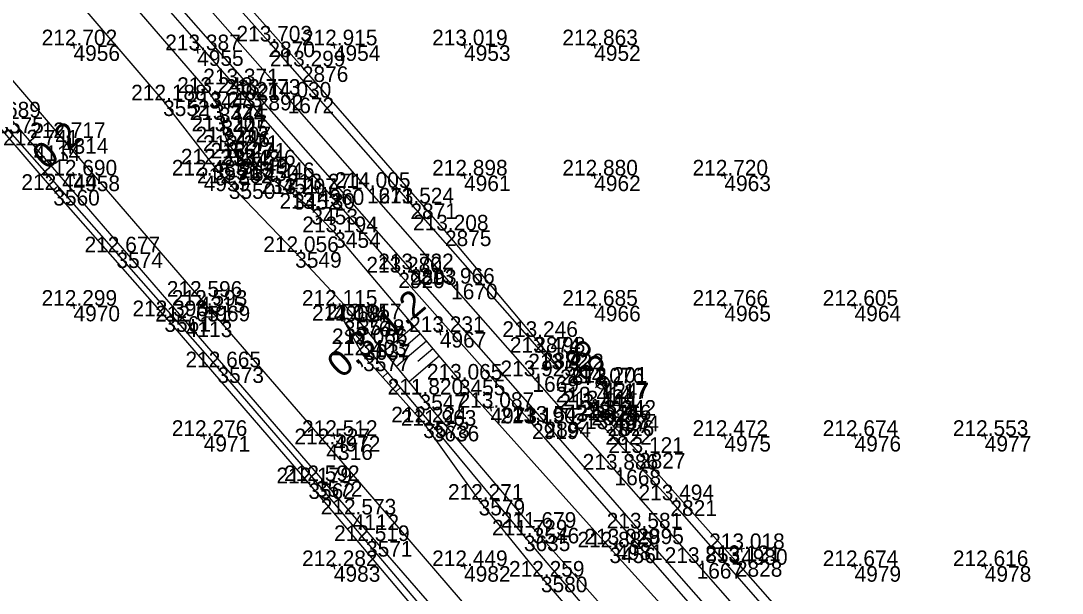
# Model space of a CAD drawing. Extents: x -556590 to -554855, y -1137918 to -1135717.
# Drawn here: x -555704 to -555624.1, y -1136452.1 to -1136408.1 of the extents above; entities that cross this region are included whole.
import ezdxf

# ---------------------------------------------------------------- set-up
doc = ezdxf.new("R2010")
doc.units = 0
for name, color, linetype in [('Vrstva 1', 7, 'Continuous'), ('Vrstva 11', 7, 'Continuous'), ('Vrstva 4', 7, 'Continuous'), ('Vrstva 48', 7, 'Continuous'), ('Vrstva 49', 7, 'Continuous'), ('Vrstva 51', 7, 'Continuous'), ('Vrstva 60', 7, 'Continuous'), ('Vrstva 61', 7, 'Continuous'), ('Vrstva 7', 7, 'Continuous')]:
    doc.layers.add(name, color=color, linetype=linetype)

msp = doc.modelspace()

# ---------------------------------------------------------------- linework, layer by layer
at = {"layer": 'Vrstva 1'}
msp.add_lwpolyline([(-555617.047, -1136489.655), (-555624.151, -1136481.584), (-555631.492, -1136473.245), (-555638.201, -1136465.612), (-555645.14, -1136457.724), (-555652.139, -1136449.756), (-555658.441, -1136442.59), (-555664.747, -1136435.415), (-555670.993, -1136428.307), (-555677.463, -1136420.947), (-555683.552, -1136414.017), (-555690.44, -1136406.179)], dxfattribs=at)
at = {"layer": 'Vrstva 11'}
for p, q in [((-555659.695, -1136435.535), (-555659.031, -1136436.291)), ((-555658.947, -1136435.632), (-555659.65, -1136435.587)), ((-555658.873, -1136436.013), (-555659.3, -1136435.985))]:
    msp.add_line(p, q, dxfattribs=at)
msp.add_circle((-555659.363, -1136435.913), 0.503, dxfattribs=at)
msp.add_arc((-555659.363, -1136435.913), 0.503, 311.31175, 131.31175, dxfattribs=at)
at = {"layer": 'Vrstva 4'}
for points in [[(-555622.431, -1136487.275), (-555632.955, -1136475.376), (-555645.659, -1136460.876), (-555652.243, -1136453.349), (-555664.779, -1136439.038), (-555675.055, -1136427.452), (-555687.678, -1136412.993), (-555700.952, -1136397.803)], [(-555696.06, -1136397.354), (-555685.031, -1136409.707), (-555674.12, -1136422.141), (-555664.029, -1136433.605), (-555662.623, -1136434.886), (-555664.606, -1136432.398), (-555671.469, -1136424.221), (-555682.46, -1136411.616), (-555693.764, -1136398.888)], [(-555697.757, -1136400.334), (-555685.919, -1136413.799), (-555674.147, -1136427.201), (-555663.818, -1136438.907), (-555656.688, -1136447.108), (-555646.98, -1136458.141), (-555633.977, -1136472.931), (-555622.465, -1136485.967)], [(-555620.12, -1136483.808), (-555629.064, -1136473.626), (-555637.092, -1136464.514), (-555645.582, -1136454.683), (-555654.149, -1136444.941), (-555659.148, -1136439.478), (-555660.228, -1136437.983), (-555660.506, -1136437.427), (-555660.012, -1136437.729), (-555658.962, -1136438.799), (-555656.562, -1136441.303), (-555649.119, -1136449.615), (-555638.104, -1136462.15), (-555629.912, -1136471.616), (-555620.889, -1136481.776)]]:
    msp.add_lwpolyline(points, dxfattribs=at)
at = {"layer": 'Vrstva 48'}
for p, q in [((-555702.177, -1136419.705), (-555702.509, -1136419.998)), ((-555701.68, -1136420.267), (-555701.85, -1136420.417)), ((-555701.184, -1136420.829), (-555701.529, -1136421.134)), ((-555700.687, -1136421.391), (-555700.86, -1136421.544)), ((-555700.19, -1136421.953), (-555700.538, -1136422.26)), ((-555673.855, -1136431.59), (-555676.13, -1136433.514)), ((-555673.371, -1136432.163), (-555674.512, -1136433.128)), ((-555672.886, -1136432.735), (-555675.179, -1136434.674)), ((-555677.25, -1136434.383), (-555676.816, -1136433.995)), ((-555671.918, -1136433.881), (-555674.228, -1136435.835)), ((-555672.402, -1136433.308), (-555673.553, -1136434.281)), ((-555676.749, -1136434.942), (-555676.541, -1136434.755)), ((-555676.248, -1136435.5), (-555675.848, -1136435.141)), ((-555675.747, -1136436.059), (-555675.556, -1136435.887)), ((-555675.247, -1136436.617), (-555674.88, -1136436.288))]:
    msp.add_line(p, q, dxfattribs=at)
at = {"layer": 'Vrstva 49'}
for p, q in [((-555699.754, -1136409.953), (-555700.246, -1136410.047)), ((-555700.047, -1136409.754), (-555699.953, -1136410.246)), ((-555679.754, -1136409.953), (-555680.246, -1136410.047)), ((-555680.047, -1136409.754), (-555679.953, -1136410.246)), ((-555669.754, -1136409.953), (-555670.246, -1136410.047)), ((-555670.047, -1136409.754), (-555669.953, -1136410.246)), ((-555659.754, -1136409.953), (-555660.246, -1136410.047)), ((-555660.047, -1136409.754), (-555659.953, -1136410.246)), ((-555690.257, -1136410.331), (-555690.749, -1136410.425)), ((-555690.55, -1136410.132), (-555690.456, -1136410.624)), ((-555699.754, -1136419.953), (-555700.246, -1136420.047)), ((-555700.047, -1136419.754), (-555699.953, -1136420.246)), ((-555689.754, -1136419.953), (-555690.246, -1136420.047)), ((-555690.047, -1136419.754), (-555689.953, -1136420.246)), ((-555669.754, -1136419.953), (-555670.246, -1136420.047)), ((-555670.047, -1136419.754), (-555669.953, -1136420.246)), ((-555659.754, -1136419.953), (-555660.246, -1136420.047)), ((-555660.047, -1136419.754), (-555659.953, -1136420.246)), ((-555649.754, -1136419.953), (-555650.246, -1136420.047)), ((-555650.047, -1136419.754), (-555649.953, -1136420.246)), ((-555680.987, -1136421.014), (-555681.479, -1136421.108)), ((-555681.28, -1136420.815), (-555681.186, -1136421.307)), ((-555699.754, -1136429.953), (-555700.246, -1136430.047)), ((-555700.047, -1136429.754), (-555699.953, -1136430.246)), ((-555689.754, -1136429.953), (-555690.246, -1136430.047)), ((-555690.047, -1136429.754), (-555689.953, -1136430.246)), ((-555679.754, -1136429.953), (-555680.246, -1136430.047)), ((-555680.047, -1136429.754), (-555679.953, -1136430.246)), ((-555659.754, -1136429.953), (-555660.246, -1136430.047)), ((-555660.047, -1136429.754), (-555659.953, -1136430.246)), ((-555649.754, -1136429.953), (-555650.246, -1136430.047)), ((-555650.047, -1136429.754), (-555649.953, -1136430.246)), ((-555639.754, -1136429.953), (-555640.246, -1136430.047)), ((-555640.047, -1136429.754), (-555639.953, -1136430.246)), ((-555671.615, -1136431.97), (-555672.107, -1136432.064)), ((-555671.908, -1136431.771), (-555671.814, -1136432.263)), ((-555667.722, -1136437.796), (-555668.214, -1136437.89)), ((-555668.015, -1136437.597), (-555667.921, -1136438.089)), ((-555658.356, -1136438.4), (-555658.848, -1136438.494)), ((-555658.649, -1136438.201), (-555658.555, -1136438.693)), ((-555689.754, -1136439.953), (-555690.246, -1136440.047)), ((-555690.047, -1136439.754), (-555689.953, -1136440.246)), ((-555679.754, -1136439.953), (-555680.246, -1136440.047)), ((-555680.047, -1136439.754), (-555679.953, -1136440.246)), ((-555649.754, -1136439.953), (-555650.246, -1136440.047)), ((-555650.047, -1136439.754), (-555649.953, -1136440.246)), ((-555639.754, -1136439.953), (-555640.246, -1136440.047)), ((-555640.047, -1136439.754), (-555639.953, -1136440.246)), ((-555629.754, -1136439.953), (-555630.246, -1136440.047)), ((-555630.047, -1136439.754), (-555629.953, -1136440.246)), ((-555658.059, -1136448.282), (-555658.551, -1136448.376)), ((-555658.352, -1136448.083), (-555658.258, -1136448.575)), ((-555648.47, -1136448.645), (-555648.962, -1136448.739)), ((-555648.763, -1136448.446), (-555648.669, -1136448.938)), ((-555679.754, -1136449.953), (-555680.246, -1136450.047)), ((-555680.047, -1136449.754), (-555679.953, -1136450.246)), ((-555669.754, -1136449.953), (-555670.246, -1136450.047)), ((-555670.047, -1136449.754), (-555669.953, -1136450.246)), ((-555639.754, -1136449.953), (-555640.246, -1136450.047)), ((-555640.047, -1136449.754), (-555639.953, -1136450.246)), ((-555629.754, -1136449.953), (-555630.246, -1136450.047)), ((-555630.047, -1136449.754), (-555629.953, -1136450.246))]:
    msp.add_line(p, q, dxfattribs=at)
for points in [[(-555615.08, -1136504.35), (-555624.636, -1136493.356), (-555633.501, -1136483.078), (-555640.265, -1136476.113), (-555648.785, -1136465.606), (-555653.585, -1136459.624), (-555664.726, -1136447.055), (-555673.42, -1136436.82), (-555678.151, -1136431.048), (-555682.973, -1136425.879), (-555688.067, -1136420.591), (-555689.304, -1136419.148), (-555693.118, -1136414.231), (-555703.25, -1136402.376)], [(-555698.73, -1136403.047), (-555689.586, -1136413.659), (-555688.83, -1136414.76), (-555688.628, -1136415.732), (-555688.486, -1136416.605), (-555688.179, -1136417.451), (-555687.7, -1136418.11), (-555687.113, -1136418.693), (-555686.288, -1136419.221), (-555684.835, -1136420.199), (-555683.123, -1136421.418), (-555681.726, -1136422.558), (-555679.975, -1136424.355), (-555670.399, -1136435.676), (-555658.834, -1136448.566), (-555650.327, -1136457.954)], [(-555643.618, -1136487.596), (-555644.451, -1136486.193), (-555652.029, -1136477.665), (-555657.009, -1136471.916), (-555667.622, -1136459.78), (-555677.531, -1136448.072), (-555681.376, -1136443.471), (-555688.944, -1136434.731), (-555696.701, -1136425.902), (-555705.857, -1136415.541), (-555707.805, -1136413.856)], [(-555707.805, -1136413.856), (-555701.555, -1136421.104), (-555693.021, -1136430.806), (-555681.957, -1136443.636), (-555672.551, -1136454.774), (-555659.833, -1136469.457), (-555649.952, -1136480.634), (-555643.618, -1136487.596)], [(-555679.234, -1136431.158), (-555677.752, -1136433.823), (-555673.144, -1136438.962), (-555668.881, -1136444.904), (-555664.096, -1136450.807), (-555655.601, -1136460.682), (-555649.17, -1136468.098), (-555646.587, -1136471.361), (-555645.564, -1136473.014), (-555644.747, -1136474.497), (-555643.95, -1136475.423), (-555642.94, -1136476.222), (-555641.262, -1136477.392), (-555640.019, -1136478.677), (-555635.816, -1136483.63), (-555627.575, -1136492.996), (-555620.189, -1136501.785)], [(-555619.626, -1136500.541), (-555625.788, -1136493.44), (-555635.233, -1136482.747), (-555640.706, -1136476.683), (-555642.014, -1136475.54), (-555642.886, -1136474.933), (-555643.62, -1136474.334), (-555644.179, -1136473.51), (-555644.832, -1136472.269), (-555645.899, -1136470.755), (-555648.036, -1136467.768), (-555654.446, -1136460.474), (-555665.404, -1136447.647), (-555672.407, -1136439.217), (-555677.696, -1136432.953), (-555679.234, -1136431.158)]]:
    msp.add_lwpolyline(points, dxfattribs=at)
at = {"layer": 'Vrstva 51'}
for points in [[(-555743.133, -1136368.314), (-555733.406, -1136379.475), (-555727.162, -1136386.762), (-555718.214, -1136397.183), (-555709.998, -1136406.534), (-555700.89, -1136417.124), (-555690.385, -1136429.309), (-555680.58, -1136440.643), (-555668.402, -1136454.771), (-555656.288, -1136468.58), (-555643.895, -1136482.917), (-555632.798, -1136495.751), (-555617.483, -1136513.593), (-555605.979, -1136526.789), (-555593.57, -1136541.12), (-555579.464, -1136557.45), (-555567.58, -1136571.183), (-555555.68, -1136584.796), (-555545.666, -1136596.303), (-555537.365, -1136605.817), (-555530.457, -1136613.715), (-555520.191, -1136625.354), (-555507.504, -1136639.736)], [(-555505.522, -1136644.883), (-555519.562, -1136629.073), (-555531.744, -1136615.155), (-555540.175, -1136605.5), (-555547.673, -1136596.899), (-555556.471, -1136586.787), (-555567.721, -1136573.974), (-555575.942, -1136564.513), (-555582.917, -1136556.401), (-555594.357, -1136543.153), (-555603.925, -1136532.234), (-555617.682, -1136516.291), (-555630.463, -1136501.491), (-555643.583, -1136486.305), (-555657.513, -1136470.232), (-555666.727, -1136459.683), (-555678.561, -1136446.033), (-555691.372, -1136431.214), (-555703.054, -1136417.695), (-555713.773, -1136405.268), (-555725.819, -1136391.439), (-555738.306, -1136376.946), (-555744.231, -1136369.998)]]:
    msp.add_lwpolyline(points, dxfattribs=at)
at = {"layer": 'Vrstva 60'}
for p, q in [((-555700, -1136410), (-555700, -1136410)), ((-555685.031, -1136409.707), (-555685.031, -1136409.707)), ((-555680, -1136410), (-555680, -1136410)), ((-555670, -1136410), (-555670, -1136410)), ((-555660, -1136410), (-555660, -1136410)), ((-555690.503, -1136410.378), (-555690.503, -1136410.378)), ((-555682.46, -1136411.616), (-555682.46, -1136411.616)), ((-555687.678, -1136412.993), (-555687.678, -1136412.993)), ((-555689.586, -1136413.659), (-555689.586, -1136413.659)), ((-555685.919, -1136413.799), (-555685.919, -1136413.799)), ((-555683.552, -1136414.017), (-555683.552, -1136414.017)), ((-555693.118, -1136414.231), (-555693.118, -1136414.231)), ((-555688.83, -1136414.76), (-555688.83, -1136414.76)), ((-555688.628, -1136415.732), (-555688.628, -1136415.732)), ((-555700.89, -1136417.124), (-555700.89, -1136417.124)), ((-555688.486, -1136416.605), (-555688.486, -1136416.605)), ((-555703.054, -1136417.695), (-555703.054, -1136417.695)), ((-555688.179, -1136417.451), (-555688.179, -1136417.451)), ((-555687.7, -1136418.11), (-555687.7, -1136418.11)), ((-555687.113, -1136418.693), (-555687.113, -1136418.693)), ((-555689.304, -1136419.148), (-555689.304, -1136419.148)), ((-555686.288, -1136419.221), (-555686.288, -1136419.221)), ((-555700, -1136420), (-555700, -1136420)), ((-555690, -1136420), (-555690, -1136420)), ((-555684.835, -1136420.199), (-555684.835, -1136420.199)), ((-555670, -1136420), (-555670, -1136420)), ((-555660, -1136420), (-555660, -1136420)), ((-555650, -1136420), (-555650, -1136420)), ((-555701.555, -1136421.104), (-555701.555, -1136421.104)), ((-555688.067, -1136420.591), (-555688.067, -1136420.591)), ((-555681.233, -1136421.061), (-555681.233, -1136421.061)), ((-555677.463, -1136420.947), (-555677.463, -1136420.947)), ((-555683.123, -1136421.418), (-555683.123, -1136421.418)), ((-555681.726, -1136422.558), (-555681.726, -1136422.558)), ((-555674.12, -1136422.141), (-555674.12, -1136422.141)), ((-555679.975, -1136424.355), (-555679.975, -1136424.355)), ((-555671.469, -1136424.221), (-555671.469, -1136424.221)), ((-555696.701, -1136425.902), (-555696.701, -1136425.902)), ((-555682.973, -1136425.879), (-555682.973, -1136425.879)), ((-555675.055, -1136427.452), (-555675.055, -1136427.452)), ((-555674.147, -1136427.201), (-555674.147, -1136427.201)), ((-555670.993, -1136428.307), (-555670.993, -1136428.307)), ((-555700, -1136430), (-555700, -1136430)), ((-555690.385, -1136429.309), (-555690.385, -1136429.309)), ((-555690, -1136430), (-555690, -1136430)), ((-555680, -1136430), (-555680, -1136430)), ((-555660, -1136430), (-555660, -1136430)), ((-555650, -1136430), (-555650, -1136430)), ((-555640, -1136430), (-555640, -1136430)), ((-555693.021, -1136430.806), (-555693.021, -1136430.806)), ((-555691.372, -1136431.214), (-555691.372, -1136431.214)), ((-555679.234, -1136431.158), (-555679.234, -1136431.158)), ((-555678.151, -1136431.048), (-555678.151, -1136431.048)), ((-555671.861, -1136432.017), (-555671.861, -1136432.017)), ((-555664.606, -1136432.398), (-555664.606, -1136432.398)), ((-555677.696, -1136432.953), (-555677.696, -1136432.953)), ((-555677.752, -1136433.823), (-555677.752, -1136433.823)), ((-555664.029, -1136433.605), (-555664.029, -1136433.605)), ((-555688.944, -1136434.731), (-555688.944, -1136434.731)), ((-555664.747, -1136435.415), (-555664.747, -1136435.415)), ((-555662.623, -1136434.886), (-555662.623, -1136434.886)), ((-555670.399, -1136435.676), (-555670.399, -1136435.676)), ((-555659.519, -1136435.97), (-555659.519, -1136435.97)), ((-555659.363, -1136435.913), (-555659.363, -1136435.913)), ((-555673.42, -1136436.82), (-555673.42, -1136436.82)), ((-555667.968, -1136437.843), (-555667.968, -1136437.843)), ((-555660.506, -1136437.427), (-555660.506, -1136437.427)), ((-555660.228, -1136437.983), (-555660.228, -1136437.983)), ((-555660.012, -1136437.729), (-555660.012, -1136437.729)), ((-555658.962, -1136438.799), (-555658.962, -1136438.799)), ((-555658.602, -1136438.447), (-555658.602, -1136438.447)), ((-555673.144, -1136438.962), (-555673.144, -1136438.962)), ((-555672.407, -1136439.217), (-555672.407, -1136439.217)), ((-555664.779, -1136439.038), (-555664.779, -1136439.038)), ((-555663.818, -1136438.907), (-555663.818, -1136438.907)), ((-555659.148, -1136439.478), (-555659.148, -1136439.478)), ((-555690, -1136440), (-555690, -1136440)), ((-555680, -1136440), (-555680, -1136440)), ((-555650, -1136440), (-555650, -1136440)), ((-555640, -1136440), (-555640, -1136440)), ((-555630, -1136440), (-555630, -1136440)), ((-555680.58, -1136440.643), (-555680.58, -1136440.643)), ((-555656.562, -1136441.303), (-555656.562, -1136441.303)), ((-555658.441, -1136442.59), (-555658.441, -1136442.59)), ((-555681.376, -1136443.471), (-555681.376, -1136443.471)), ((-555681.957, -1136443.636), (-555681.957, -1136443.636)), ((-555668.881, -1136444.904), (-555668.881, -1136444.904)), ((-555654.149, -1136444.941), (-555654.149, -1136444.941)), ((-555678.561, -1136446.033), (-555678.561, -1136446.033)), ((-555664.726, -1136447.055), (-555664.726, -1136447.055)), ((-555656.688, -1136447.108), (-555656.688, -1136447.108)), ((-555677.531, -1136448.072), (-555677.531, -1136448.072)), ((-555665.404, -1136447.647), (-555665.404, -1136447.647)), ((-555658.305, -1136448.329), (-555658.305, -1136448.329)), ((-555658.834, -1136448.566), (-555658.834, -1136448.566)), ((-555648.716, -1136448.692), (-555648.716, -1136448.692)), ((-555680, -1136450), (-555680, -1136450)), ((-555670, -1136450), (-555670, -1136450)), ((-555652.139, -1136449.756), (-555652.139, -1136449.756)), ((-555649.119, -1136449.615), (-555649.119, -1136449.615)), ((-555640, -1136450), (-555640, -1136450)), ((-555630, -1136450), (-555630, -1136450)), ((-555664.096, -1136450.807), (-555664.096, -1136450.807))]:
    msp.add_line(p, q, dxfattribs=at)
at = {"layer": 'Vrstva 7'}
for p, q in [((-555659.849, -1136435.594), (-555659.189, -1136436.346)), ((-555659.143, -1136435.64), (-555659.895, -1136436.3))]:
    msp.add_line(p, q, dxfattribs=at)

# ---------------------------------------------------------------- texts
at = {"layer": 'Vrstva 11'}
msp.add_text('38', height=2, rotation=131.31175, dxfattribs=at).set_placement((-555659, -1136434.645))
at = {"layer": 'Vrstva 48'}
for s, rotation, p in [('0,2', 41.46698, (-555702.065, -1136419.651)), ('1,2', 40.2266, (-555675.625, -1136432.532)), ('0,3', 41.88171, (-555679.401, -1136435.642))]:
    msp.add_text(s, height=2, rotation=rotation, dxfattribs=at).set_placement(p)
at = {"layer": 'Vrstva 60'}
for s, p in [('4956', (-555700, -1136411.2)), ('2870', (-555685.031, -1136410.907)), ('4954', (-555680, -1136411.2)), ('4953', (-555670, -1136411.2)), ('4952', (-555660, -1136411.2)), ('4955', (-555690.503, -1136411.578)), ('2876', (-555682.46, -1136412.816)), ('2921', (-555687.678, -1136414.193)), ('3443', (-555689.586, -1136414.859)), ('2892', (-555685.919, -1136414.999)), ('1672', (-555683.552, -1136415.217)), ('3552', (-555693.118, -1136415.431)), ('3444', (-555688.83, -1136415.96)), ('3575', (-555705.857, -1136416.741)), ('3445', (-555688.628, -1136416.932)), ('4314', (-555700.89, -1136418.324)), ('3446', (-555688.486, -1136417.805)), ('4114', (-555703.054, -1136418.895)), ('3447', (-555688.179, -1136418.651)), ('3448', (-555687.7, -1136419.31)), ('3449', (-555687.113, -1136419.893)), ('3551', (-555689.304, -1136420.348)), ('3450', (-555686.288, -1136420.421)), ('4958', (-555700, -1136421.2)), ('4959', (-555690, -1136421.2)), ('3451', (-555684.835, -1136421.399)), ('4961', (-555670, -1136421.2)), ('4962', (-555660, -1136421.2)), ('4963', (-555650, -1136421.2)), ('3560', (-555701.555, -1136422.304)), ('3550', (-555688.067, -1136421.791)), ('4960', (-555681.233, -1136422.261)), ('1671', (-555677.463, -1136422.147)), ('3452', (-555683.123, -1136422.618)), ('3453', (-555681.726, -1136423.758)), ('2871', (-555674.12, -1136423.341)), ('3454', (-555679.975, -1136425.555)), ('2875', (-555671.469, -1136425.421)), ('3574', (-555696.701, -1136427.102)), ('3549', (-555682.973, -1136427.079)), ('2920', (-555675.055, -1136428.652)), ('2893', (-555674.147, -1136428.401)), ('1670', (-555670.993, -1136429.507)), ('4970', (-555700, -1136431.2)), ('4315', (-555690.385, -1136430.509)), ('4969', (-555690, -1136431.2)), ('4968', (-555680, -1136431.2)), ('4966', (-555660, -1136431.2)), ('4965', (-555650, -1136431.2)), ('4964', (-555640, -1136431.2)), ('3561', (-555693.021, -1136432.006)), ('4113', (-555691.372, -1136432.414)), ('3576', (-555679.234, -1136432.358)), ('3548', (-555678.151, -1136432.248)), ('4967', (-555671.861, -1136433.217)), ('2874', (-555664.606, -1136433.598)), ('3637', (-555677.696, -1136434.153)), ('3577', (-555677.752, -1136435.023)), ('2872', (-555664.029, -1136434.805)), ('3573', (-555688.944, -1136435.931)), ('1669', (-555664.747, -1136436.615)), ('2873', (-555662.623, -1136436.086)), ('3455', (-555670.399, -1136436.876)), ('1517', (-555659.519, -1136437.17)), ('4247', (-555659.363, -1136437.113)), ('3547', (-555673.42, -1136438.02)), ('4973', (-555667.968, -1136439.043)), ('2824', (-555660.506, -1136438.627)), ('2823', (-555660.228, -1136439.183)), ('2825', (-555660.012, -1136438.929)), ('2826', (-555658.962, -1136439.999)), ('4974', (-555658.602, -1136439.647)), ('3578', (-555673.144, -1136440.162)), ('3636', (-555672.407, -1136440.417)), ('2919', (-555664.779, -1136440.238)), ('2894', (-555663.818, -1136440.107)), ('2822', (-555659.148, -1136440.678)), ('4971', (-555690, -1136441.2)), ('4972', (-555680, -1136441.2)), ('4975', (-555650, -1136441.2)), ('4976', (-555640, -1136441.2)), ('4977', (-555630, -1136441.2)), ('4316', (-555680.58, -1136441.843)), ('2827', (-555656.562, -1136442.503)), ('1668', (-555658.441, -1136443.79)), ('3562', (-555681.957, -1136444.836)), ('3572', (-555681.376, -1136444.671)), ('3579', (-555668.881, -1136446.104)), ('2821', (-555654.149, -1136446.141)), ('4112', (-555678.561, -1136447.233)), ('3635', (-555665.404, -1136448.847)), ('3546', (-555664.726, -1136448.255)), ('2895', (-555656.688, -1136448.308)), ('3571', (-555677.531, -1136449.272)), ('4981', (-555658.305, -1136449.529)), ('3456', (-555658.834, -1136449.766)), ('4980', (-555648.716, -1136449.892)), ('4983', (-555680, -1136451.2)), ('4982', (-555670, -1136451.2)), ('1667', (-555652.139, -1136450.956)), ('2828', (-555649.119, -1136450.815)), ('4979', (-555640, -1136451.2)), ('4978', (-555630, -1136451.2)), ('3580', (-555664.096, -1136452.007))]:
    msp.add_text(s, height=1.2, dxfattribs=at).set_placement(p)
at = {"layer": 'Vrstva 61'}
for s, p in [('212.702', (-555702.448, -1136410)), ('213.387', (-555692.955, -1136410.378)), ('213.703', (-555687.483, -1136409.707)), ('212.915', (-555682.456, -1136410)), ('213.019', (-555672.454, -1136410)), ('212.863', (-555662.452, -1136410)), ('213.299', (-555684.914, -1136411.616)), ('213.371', (-555690.035, -1136412.993)), ('212.188', (-555695.572, -1136414.231)), ('213.248', (-555692.04, -1136413.659)), ('213.773', (-555688.371, -1136413.799)), ('214.030', (-555686.003, -1136414.017)), ('213.273', (-555691.282, -1136414.76)), ('212.689', (-555708.311, -1136415.541)), ('213.324', (-555691.079, -1136415.732)), ('213.207', (-555690.938, -1136416.605)), ('212.717', (-555703.342, -1136417.124)), ('213.207', (-555690.631, -1136417.451)), ('212.741', (-555705.411, -1136417.695)), ('213.271', (-555690.057, -1136418.11)), ('212.333', (-555691.756, -1136419.148)), ('213.271', (-555689.47, -1136418.693)), ('213.246', (-555688.74, -1136419.221)), ('212.690', (-555702.451, -1136420)), ('212.483', (-555692.452, -1136420)), ('212.898', (-555672.454, -1136420)), ('212.880', (-555662.451, -1136420)), ('212.720', (-555652.451, -1136420)), ('212.262', (-555690.515, -1136420.591)), ('213.246', (-555687.287, -1136420.199)), ('212.444', (-555704.006, -1136421.104)), ('213.207', (-555685.575, -1136421.418)), ('213.271', (-555683.59, -1136421.061)), ('214.005', (-555679.919, -1136420.947)), ('213.524', (-555676.571, -1136422.141)), ('213.130', (-555684.177, -1136422.558)), ('213.194', (-555682.426, -1136424.355)), ('213.208', (-555673.923, -1136424.221)), ('212.677', (-555699.153, -1136425.902)), ('212.056', (-555685.425, -1136425.879)), ('213.722', (-555676.595, -1136427.201)), ('213.280', (-555677.506, -1136427.452)), ('213.966', (-555673.445, -1136428.307)), ('212.596', (-555692.837, -1136429.309)), ('212.299', (-555702.454, -1136430)), ('212.593', (-555692.452, -1136430)), ('212.115', (-555682.456, -1136430)), ('212.685', (-555662.456, -1136430)), ('212.766', (-555652.452, -1136430)), ('212.605', (-555642.456, -1136430)), ('212.396', (-555695.473, -1136430.806)), ('212.651', (-555693.729, -1136431.214)), ('212.084', (-555681.685, -1136431.158)), ('212.057', (-555680.603, -1136431.048)), ('213.231', (-555674.218, -1136432.017)), ('213.246', (-555667.058, -1136432.398)), ('212.066', (-555680.148, -1136432.953)), ('213.498', (-555666.483, -1136433.605)), ('212.403', (-555680.204, -1136433.823)), ('212.665', (-555691.4, -1136434.731)), ('213.422', (-555665.071, -1136434.886)), ('213.065', (-555672.855, -1136435.676)), ('213.925', (-555667.203, -1136435.415)), ('214.076', (-555661.971, -1136435.97)), ('213.201', (-555661.72, -1136435.913)), ('211.820', (-555675.871, -1136436.82)), ('213.414', (-555662.957, -1136437.427)), ('213.087', (-555670.42, -1136437.843)), ('213.449', (-555662.682, -1136437.983)), ('213.111', (-555662.369, -1136437.729)), ('213.242', (-555661.05, -1136438.447)), ('212.224', (-555675.595, -1136438.962)), ('211.963', (-555674.859, -1136439.217)), ('213.190', (-555667.23, -1136439.038)), ('213.543', (-555666.27, -1136438.907)), ('213.146', (-555661.414, -1136438.799)), ('212.276', (-555692.452, -1136440)), ('212.512', (-555682.448, -1136440)), ('213.483', (-555661.6, -1136439.478)), ('212.472', (-555652.448, -1136440)), ('212.674', (-555642.451, -1136440)), ('212.553', (-555632.452, -1136440)), ('212.527', (-555683.032, -1136440.643)), ('213.121', (-555658.919, -1136441.303)), ('213.886', (-555660.893, -1136442.59)), ('212.179', (-555684.411, -1136443.636)), ('212.592', (-555683.824, -1136443.471)), ('212.271', (-555671.238, -1136444.904)), ('213.494', (-555656.6, -1136444.941)), ('212.573', (-555681.013, -1136446.033)), ('211.679', (-555667.18, -1136447.055)), ('213.581', (-555659.045, -1136447.108)), ('211.729', (-555667.858, -1136447.647)), ('212.519', (-555679.985, -1136448.072)), ('212.885', (-555661.29, -1136448.566)), ('213.029', (-555660.759, -1136448.329)), ('213.018', (-555651.17, -1136448.692)), ('213.121', (-555651.476, -1136449.615)), ('212.282', (-555682.448, -1136450)), ('212.449', (-555672.454, -1136450)), ('213.853', (-555654.591, -1136449.756)), ('212.674', (-555642.451, -1136450)), ('212.616', (-555632.452, -1136450)), ('212.259', (-555666.55, -1136450.807))]:
    msp.add_text(s, height=1.2, dxfattribs=at).set_placement(p)

doc.saveas('drawing.dxf')
